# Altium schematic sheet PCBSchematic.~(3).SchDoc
size Letter; SheetNumber: 1; SheetTotal: 1
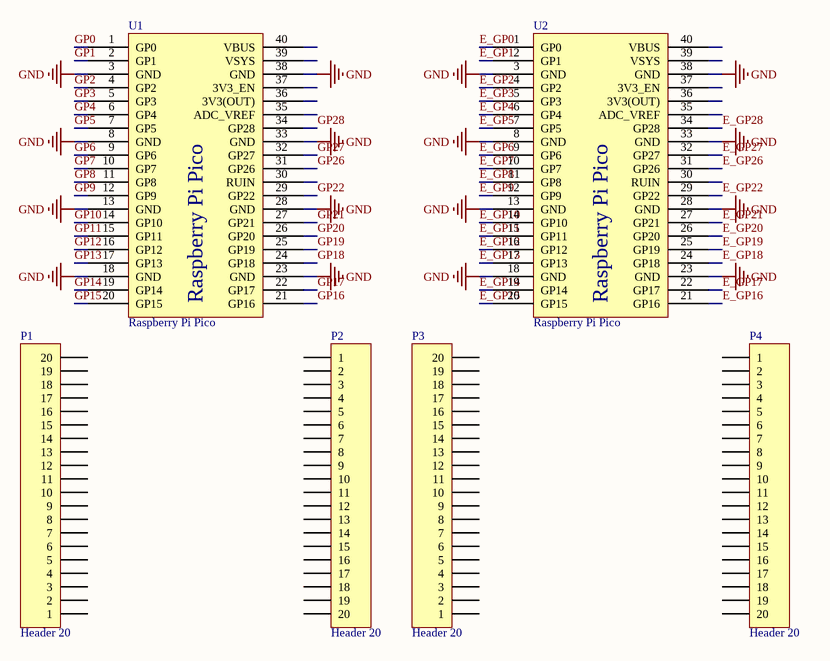
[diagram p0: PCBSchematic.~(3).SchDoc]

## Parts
P1  Header 20  [HDR1X20]
P2  Header 20  [HDR1X20]
P3  Header 20  [HDR1X20]
P4  Header 20  [HDR1X20]
U1  Raspberry Pi Pico  [Raspberry Pi Pico]
U2  Raspberry Pi Pico  [Raspberry Pi Pico]

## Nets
GND: U1.3(GND) U1.8(GND) U1.13(GND) U1.18(GND) U1.23(GND) U1.28(GND) U1.33(GND) U1.38(GND) U2.3(GND) U2.8(GND) U2.13(GND) U2.18(GND) U2.23(GND) U2.28(GND) U2.33(GND) U2.38(GND)
E_GP0: U2.1(GP0)
E_GP1: U2.2(GP1)
E_GP2: U2.4(GP2)
E_GP3: U2.5(GP3)
E_GP4: U2.6(GP4)
E_GP5: U2.7(GP5)
E_GP6: U2.9(GP6)
E_GP7: U2.10(GP7)
E_GP8: U2.11(GP8)
E_GP9: U2.12(GP9)
E_GP10: U2.14(GP10)
E_GP11: U2.15(GP11)
E_GP12: U2.16(GP12)
E_GP13: U2.17(GP13)
E_GP14: U2.19(GP14)
E_GP15: U2.20(GP15)
E_GP16: U2.21(GP16)
E_GP17: U2.22(GP17)
E_GP18: U2.24(GP18)
E_GP19: U2.25(GP19)
E_GP20: U2.26(GP20)
E_GP21: U2.27(GP21)
E_GP22: U2.29(GP22)
E_GP26: U2.31(GP26)
E_GP27: U2.32(GP27)
E_GP28: U2.34(GP28)
GP0: U1.1(GP0)
GP1: U1.2(GP1)
GP2: U1.4(GP2)
GP3: U1.5(GP3)
GP4: U1.6(GP4)
GP5: U1.7(GP5)
GP6: U1.9(GP6)
GP7: U1.10(GP7)
GP8: U1.11(GP8)
GP9: U1.12(GP9)
GP10: U1.14(GP10)
GP11: U1.15(GP11)
GP12: U1.16(GP12)
GP13: U1.17(GP13)
GP14: U1.19(GP14)
GP15: U1.20(GP15)
GP16: U1.21(GP16)
GP17: U1.22(GP17)
GP18: U1.24(GP18)
GP19: U1.25(GP19)
GP20: U1.26(GP20)
GP21: U1.27(GP21)
GP22: U1.29(GP22)
GP26: U1.31(GP26)
GP27: U1.32(GP27)
GP28: U1.34(GP28)

Not connected (* = marked no-connect by the designer): P1 1 2 3 4 5 6 7 8 9 10 11 12 13 14 15 16 17 18 19 20; P2 1 2 3 4 5 6 7 8 9 10 11 12 13 14 15 16 17 18 19 20; P3 1 2 3 4 5 6 7 8 9 10 11 12 13 14 15 16 17 18 19 20; P4 1 2 3 4 5 6 7 8 9 10 11 12 13 14 15 16 17 18 19 20; U1 30(RUIN) 35(ADC_VREF) 36(3V3(OUT)) 37(3V3_EN) 39(VSYS) 40(VBUS); U2 30(RUIN) 35(ADC_VREF) 36(3V3(OUT)) 37(3V3_EN) 39(VSYS) 40(VBUS)

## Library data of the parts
P1-P4 = Header 20: Header, 20-Pin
